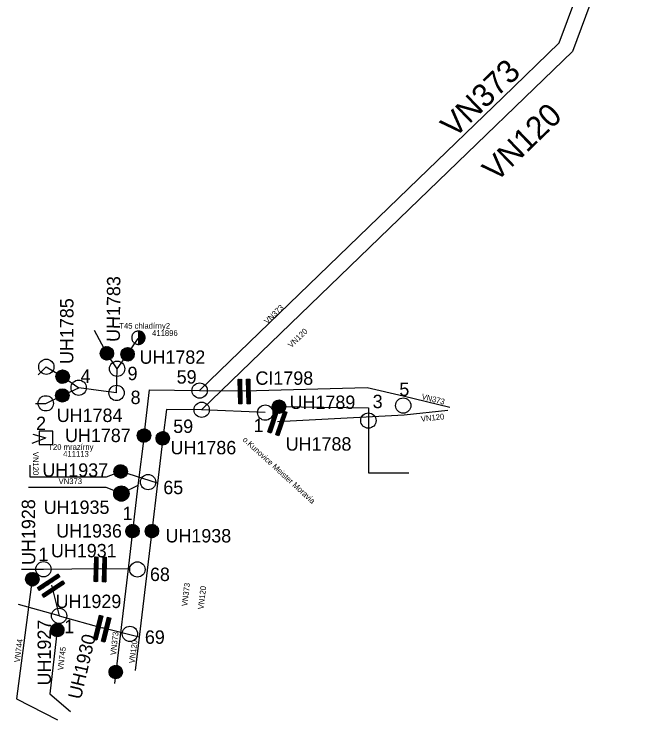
# Model space of a CAD drawing. Extents: x -540356 to -537233, y -1184040 to -1180351.
# Drawn here: x -540356 to -538730, y -1184040 to -1182196 of the extents above; entities that cross this region are included whole.
import ezdxf

# ---------------------------------------------------------------- set-up
doc = ezdxf.new("R2010")
doc.units = 0
for name, color, linetype in [('Default', 7, 'Continuous'), ('Vrstva 1', 7, 'Continuous'), ('Vrstva 2', 7, 'Continuous'), ('Vrstva 20', 7, 'Continuous'), ('Vrstva 3', 7, 'Continuous'), ('Vrstva 5', 7, 'Continuous')]:
    doc.layers.add(name, color=color, linetype=linetype)

# ---------------------------------------------------------------- blocks, each defined once
blk = doc.blocks.new('PS100')
at = {"layer": 'Default'}
for p, q in [((-17.5, -0.7), (0.7, 17.5)), ((-17.5, 0.7), (-0.7, 17.5)), ((-17.4, -2), (2, 17.4)), ((-17.3, 2.2), (-2.2, 17.3)), ((-17.2, -3.3), (3.3, 17.2)), ((-17, 4), (-4, 17)), ((-16.9, -4.4), (4.4, 16.9)), ((-16.6, -5.5), (5.5, 16.6)), ((-16.4, 6), (-6, 16.4)), ((-16.2, -6.5), (6.5, 16.2)), ((-15.8, -7.5), (7.5, 15.8)), ((-15.3, -8.4), (8.4, 15.3)), ((-15.2, 8.6), (-8.6, 15.2)), ((-14.8, -9.3), (9.3, 14.8)), ((-14.2, -10.2), (10.2, 14.2)), ((-13.6, -11), (11, 13.6)), ((-13, -11.7), (11.7, 13)), ((-12.3, -12.5), (12.5, 12.3)), ((-11.5, -13.2), (13.2, 11.5)), ((-10.8, -13.8), (13.8, 10.8)), ((-9.9, -14.4), (14.4, 9.9)), ((-9.1, -14.9), (14.9, 9.1)), ((-8.2, -15.5), (15.5, 8.2)), ((-7.2, -15.9), (15.9, 7.2)), ((-6.2, -16.3), (16.3, 6.2)), ((-5.2, -16.7), (16.7, 5.2)), ((-4.1, -17), (17, 4.1)), ((-2.9, -17.2), (17.2, 2.9)), ((-1.6, -17.4), (17.4, 1.6)), ((-0.3, -17.5), (17.5, 0.3)), ((1.1, -17.4), (17.4, -1.1)), ((2.7, -17.3), (17.3, -2.7)), ((4.5, -16.9), (16.9, -4.5)), ((6.7, -16.2), (16.2, -6.7)), ((9.7, -14.5), (14.5, -9.7))]:
    blk.add_line(p, q, dxfattribs=at)
blk.add_circle((0, 0), 17.5, dxfattribs=at)
blk = doc.blocks.new('PS140')
at = {"layer": 'Default'}
for p, q in [((-17.5, 0), (0, 17.5)), ((-17.4, -1.4), (1.4, 17.4)), ((-17.4, 1.5), (-1.5, 17.4)), ((-17.3, -2.6), (2.6, 17.3)), ((-17.2, 3.1), (-3.1, 17.2)), ((-17.1, -3.8), (3.8, 17.1)), ((-16.8, -4.9), (4.9, 16.8)), ((-16.8, 5), (-5, 16.8)), ((-16.4, -6), (6, 16.4)), ((-16, -7), (7, 16)), ((-15.9, 7.2), (-7.2, 15.9)), ((-15.6, -8), (8, 15.6)), ((-15.1, -8.9), (8.9, 15.1)), ((-14.5, -9.8), (9.8, 14.5)), ((-13.9, -10.6), (10.6, 13.9)), ((-13.8, 10.8), (-10.8, 13.8)), ((-13.3, -11.4), (11.4, 13.3)), ((-12.6, -12.1), (12.1, 12.6)), ((-11.9, -12.8), (12.8, 11.9)), ((-11.2, -13.5), (13.5, 11.2)), ((-10.4, -14.1), (14.1, 10.4)), ((-9.5, -14.7), (14.7, 9.5)), ((-8.6, -15.2), (15.2, 8.6)), ((-7.7, -15.7), (15.7, 7.7)), ((-6.7, -16.1), (16.1, 6.7)), ((-5.7, -16.5), (16.5, 5.7)), ((-4.6, -16.9), (16.9, 4.6)), ((-3.5, -17.1), (17.1, 3.5)), ((-2.3, -17.3), (17.3, 2.3)), ((-1, -17.5), (17.5, 1)), ((0.4, -17.5), (17.5, -0.4)), ((1.9, -17.4), (17.4, -1.9)), ((3.6, -17.1), (17.1, -3.6)), ((5.5, -16.6), (16.6, -5.5)), ((8, -15.6), (15.6, -8))]:
    blk.add_line(p, q, dxfattribs=at)
blk.add_circle((0, 0), 17.5, dxfattribs=at)
blk = doc.blocks.new('PS150')
at = {"layer": 'Default'}
for p, q in [((-15.1, 22.4), (-7.4, 30.1)), ((-15.1, 23.8), (-8.8, 30.1)), ((-15.1, 25.2), (-10.2, 30.1)), ((-15.1, 26.6), (-11.6, 30.1)), ((-15.1, 28), (-13, 30.1)), ((-15.1, 29.4), (-14.4, 30.1)), ((-15.1, 20.9), (-6.5, 29.5)), ((-15.1, 19.5), (-6.5, 28.1)), ((-15.1, 18.1), (-6.5, 26.7)), ((-15.1, 16.7), (-6.5, 25.3)), ((-15.1, 15.3), (-6.5, 23.9)), ((-15.1, 13.9), (-6.5, 22.4)), ((-15.1, 12.5), (-6.5, 21)), ((-15.1, 11), (-6.5, 19.6)), ((6.7, 22.6), (14.1, 30.1)), ((6.7, 24), (12.7, 30.1)), ((6.7, 25.4), (11.3, 30.1)), ((6.7, 26.8), (9.9, 30.1)), ((6.7, 28.3), (8.5, 30.1)), ((6.7, 29.7), (7, 30.1)), ((6.7, 21.2), (15.2, 29.8)), ((6.7, 19.8), (15.2, 28.3)), ((6.7, 18.4), (15.2, 26.9)), ((6.7, 16.9), (15.2, 25.5)), ((6.7, 15.5), (15.2, 24.1)), ((6.7, 14.1), (15.2, 22.7)), ((6.7, 12.7), (15.2, 21.3)), ((6.7, 11.3), (15.2, 19.9)), ((6.7, 9.9), (15.2, 18.4)), ((-15.1, 9.6), (-6.5, 18.2)), ((-15.1, 8.2), (-6.5, 16.8)), ((-15.1, 6.8), (-6.5, 15.4)), ((-15.1, 5.4), (-6.5, 14)), ((-15.1, 4), (-6.5, 12.5)), ((-15.1, 2.6), (-6.5, 11.1)), ((-15.1, 1.2), (-6.5, 9.7)), ((-15.1, -0.3), (-6.5, 8.3)), ((-15.1, -1.7), (-6.5, 6.9)), ((-15.1, -3.1), (-6.5, 5.5)), ((-15.1, -4.5), (-6.5, 4.1)), ((-15.1, -5.9), (-6.5, 2.6)), ((-15.1, -7.3), (-6.5, 1.2)), ((6.7, 8.5), (15.2, 17)), ((6.7, 7.1), (15.2, 15.6)), ((6.7, 5.6), (15.2, 14.2)), ((6.7, 4.2), (15.2, 12.8)), ((6.7, 2.8), (15.2, 11.4)), ((6.7, 1.4), (15.2, 10)), ((6.7, 0), (15.2, 8.5)), ((6.7, -1.4), (15.2, 7.1)), ((6.7, -2.8), (15.2, 5.7)), ((6.7, -4.3), (15.2, 4.3)), ((6.7, -5.7), (15.2, 2.9)), ((6.7, -7.1), (15.2, 1.5)), ((6.7, -8.5), (15.2, 0.1)), ((-15.1, -8.7), (-6.5, -0.2)), ((-15.1, -10.2), (-6.5, -1.6)), ((-15.1, -11.6), (-6.5, -3)), ((-15.1, -13), (-6.5, -4.4)), ((-15.1, -14.4), (-6.5, -5.8)), ((-15.1, -15.8), (-6.5, -7.3)), ((-15.1, -17.2), (-6.5, -8.7)), ((-15.1, -18.6), (-6.5, -10.1)), ((-15.1, -20.1), (-6.5, -11.5)), ((-15.1, -21.5), (-6.5, -12.9)), ((-15.1, -22.9), (-6.5, -14.3)), ((-15.1, -24.3), (-6.5, -15.7)), ((-15.1, -25.7), (-6.5, -17.2)), ((6.7, -9.9), (15.2, -1.4)), ((6.7, -11.3), (15.2, -2.8)), ((6.7, -12.7), (15.2, -4.2)), ((6.7, -14.2), (15.2, -5.6)), ((6.7, -15.6), (15.2, -7)), ((6.7, -17), (15.2, -8.4)), ((6.7, -18.4), (15.2, -9.8)), ((6.7, -19.8), (15.2, -11.3)), ((6.7, -21.2), (15.2, -12.7)), ((6.7, -22.6), (15.2, -14.1)), ((6.7, -24.1), (15.2, -15.5)), ((6.7, -25.5), (15.2, -16.9)), ((6.7, -26.9), (15.2, -18.3)), ((-15.1, -27.1), (-6.5, -18.6)), ((-15.1, -28.5), (-6.5, -20)), ((-15.1, -30), (-6.5, -21.4)), ((-15.1, -31.4), (-6.5, -22.8)), ((-15.1, -32.8), (-6.5, -24.2)), ((-15, -34.2), (-6.5, -25.6)), ((-13.6, -34.2), (-6.5, -27.1)), ((-12.2, -34.2), (-6.5, -28.5)), ((-10.8, -34.2), (-6.5, -29.9)), ((-9.4, -34.2), (-6.5, -31.3)), ((-8, -34.2), (-6.5, -32.7)), ((-6.5, -34.2), (-6.5, -34.1)), ((6.7, -28.3), (15.2, -19.7)), ((6.7, -29.7), (15.2, -21.2)), ((6.7, -31.1), (15.2, -22.6)), ((6.7, -32.5), (15.2, -24)), ((6.7, -34), (15.2, -25.4)), ((7.9, -34.2), (15.2, -26.8)), ((9.3, -34.2), (15.2, -28.2)), ((10.7, -34.2), (15.2, -29.6)), ((12.1, -34.2), (15.2, -31)), ((13.5, -34.2), (15.2, -32.5)), ((14.9, -34.2), (15.2, -33.9))]:
    blk.add_line(p, q, dxfattribs=at)
for points in [[(-6.5, 30.1), (-6.5, -34.2), (-15.1, -34.2), (-15.1, 30.1)], [(15.2, 30.1), (15.2, -34.2), (6.7, -34.2), (6.7, 30.1)]]:
    blk.add_lwpolyline(points, close=True, dxfattribs=at)
blk = doc.blocks.new('PS800')
at = {"layer": 'Vrstva 2'}
blk.add_circle((0, 0), 20, dxfattribs=at)
blk = doc.blocks.new('PS650')
at = {"layer": 'Vrstva 20'}
for points in [[(17.5, 17.5), (-17.5, 17.5)], [(-17.5, 17.5), (-17.5, -17.5)], [(17.5, -17.5), (17.5, 17.5)], [(-17.5, -17.5), (17.5, -17.5)]]:
    blk.add_lwpolyline(points, dxfattribs=at)
blk = doc.blocks.new('PS611')
at = {"layer": 'Default'}
for p, q in [((0, 16.2), (1.3, 17.4)), ((0, 14.7), (2.5, 17.3)), ((0, 13.3), (3.7, 17.1)), ((0, 11.9), (4.9, 16.8)), ((0, 10.5), (5.9, 16.4)), ((0, 9.1), (7, 16)), ((0, 7.7), (7.9, 15.6)), ((0, 6.3), (8.8, 15.1)), ((0, 4.8), (9.7, 14.5)), ((0, 3.4), (10.5, 14)), ((0, 2), (11.3, 13.3)), ((0, 0.6), (12, 12.7)), ((0, -0.8), (12.8, 12)), ((0, -2.2), (13.4, 11.2)), ((0, -3.6), (14, 10.4)), ((0, -5), (14.6, 9.6)), ((0, -6.5), (15.2, 8.7)), ((0, -7.9), (15.6, 7.8)), ((0, -9.3), (16.1, 6.8)), ((0, -10.7), (16.5, 5.8)), ((0, -12.1), (16.8, 4.7)), ((0, -13.5), (17.1, 3.6)), ((0, -14.9), (17.3, 2.4)), ((0, -16.4), (17.4, 1.1)), ((0.3, -17.5), (17.5, -0.3)), ((1.8, -17.4), (17.4, -1.8)), ((3.5, -17.1), (17.1, -3.5)), ((5.4, -16.7), (16.7, -5.4)), ((7.8, -15.7), (15.6, -7.8))]:
    blk.add_line(p, q, dxfattribs=at)
for points in [[(17.5, 0), (17.4, 1.8), (17.1, 3.6), (16.6, 5.4), (16, 7.1), (15.2, 8.8), (14.2, 10.3), (13, 11.7), (11.7, 13), (10.3, 14.2), (8.7, 15.2), (7.1, 16), (5.4, 16.6), (3.6, 17.1), (1.8, 17.4), (0, 17.5), (-1.8, 17.4), (-3.6, 17.1), (-5.4, 16.6), (-7.1, 16), (-8.8, 15.2), (-10.3, 14.2), (-11.7, 13), (-13, 11.7), (-14.2, 10.3), (-15.2, 8.7), (-16, 7.1), (-16.6, 5.4), (-17.1, 3.6), (-17.4, 1.8), (-17.5, 0), (-17.4, -1.8), (-17.1, -3.6), (-16.6, -5.4), (-16, -7.1), (-15.2, -8.8), (-14.2, -10.3), (-13, -11.7), (-11.7, -13), (-10.3, -14.2), (-8.8, -15.2), (-7.1, -16), (-5.4, -16.6), (-3.6, -17.1), (-1.8, -17.4), (0, -17.5), (1.8, -17.4), (3.6, -17.1), (5.4, -16.6), (7.1, -16), (8.8, -15.2), (10.3, -14.2), (11.7, -13), (13, -11.7), (14.2, -10.3), (15.2, -8.8), (16, -7.1), (16.6, -5.4), (17.1, -3.6), (17.4, -1.8), (17.5, 0)], [(0, 17.5), (0, -17.5)]]:
    blk.add_lwpolyline(points, dxfattribs=at)

msp = doc.modelspace()

# ---------------------------------------------------------------- linework, layer by layer
at = {"layer": 'Vrstva 1'}
for points in [[(-538730.2, -1181781.1), (-538745.8, -1181888.8), (-538896.2, -1182293.4), (-539271.4, -1182655.8), (-539865.4, -1183229.4)], [(-539078.2, -1182413.6), (-538930.5, -1182270.9), (-538802.3, -1181926.1), (-538823.3, -1181857.6)], [(-539298.4, -1182626.3), (-539078.2, -1182413.6)], [(-539870.7, -1183179.1), (-539298.4, -1182626.3)], [(-540113.1, -1183082), (-540145.5, -1183022.4)], [(-540059.1, -1183084.2), (-540031.4, -1183042.7)], [(-540086.3, -1183122.1), (-540113.1, -1183082)], [(-540086.3, -1183122.1), (-540059.1, -1183084.2)], [(-540293.2, -1183137.8), (-540271.5, -1183117.1)], [(-540271.5, -1183117.1), (-540228.8, -1183142.7)], [(-540087.9, -1183185.4), (-540086.3, -1183122.1)], [(-540228.8, -1183142.7), (-540186.9, -1183171.6)], [(-540229.7, -1183191.8), (-540186.9, -1183171.6)], [(-540135.2, -1183178.8), (-540186.9, -1183171.6)], [(-540087.9, -1183185.4), (-540135.2, -1183178.8)], [(-540016.1, -1183296.7), (-540001.7, -1183177.6), (-539870.7, -1183179.1)], [(-539870.7, -1183179.1), (-539754.1, -1183179.6)], [(-539754.1, -1183179.6), (-539433, -1183171.4), (-539338.5, -1183192.6)], [(-540272.9, -1183212.5), (-540229.7, -1183191.8)], [(-539338.5, -1183192.6), (-539216.9, -1183222.3)], [(-540299.6, -1183212.5), (-540272.9, -1183212.5)], [(-539865.4, -1183229.4), (-539957.4, -1183228.3), (-539967, -1183303.9)], [(-539699, -1183236.8), (-539865.4, -1183229.4), (-539865.4, -1183229.4)], [(-539663.2, -1183221.2), (-539429.6, -1183224.5), (-539429.6, -1183393.8), (-539324, -1183393.8)], [(-539335.9, -1183242.5), (-539221.9, -1183230.2)], [(-539666.8, -1183259.6), (-539335.9, -1183242.5)], [(-540308.5, -1183316.2), (-540272.4, -1183302.6)], [(-540306.5, -1183293.2), (-540272.4, -1183302.6)], [(-540016.1, -1183296.7), (-540032.2, -1183427.6)], [(-539967, -1183303.9), (-539980.5, -1183421.3)], [(-540077.1, -1183390.5), (-540115.2, -1183405.7), (-540313.4, -1183405.6), (-540313.4, -1183373.7)], [(-539980.5, -1183421.3), (-540077.1, -1183390.5)], [(-540075.3, -1183448.2), (-540115.1, -1183432.6), (-540318.4, -1183432.7)], [(-540032.1, -1183427.6), (-540075.3, -1183448.2)], [(-540032.1, -1183427.6), (-540046, -1183546.3)], [(-539980.5, -1183421.3), (-539995.6, -1183546.3)], [(-540046, -1183546.3), (-540057.8, -1183644.9)], [(-539995.6, -1183546.3), (-540028.8, -1183823.3)], [(-540336.7, -1183646.1), (-540278.9, -1183646)], [(-540278.9, -1183646), (-540130.6, -1183644.3)], [(-540130.6, -1183644.3), (-540057.8, -1183644.9)], [(-540057.8, -1183644.9), (-540090, -1183914.6)], [(-540308.1, -1183671.6), (-540349.2, -1183984.9), (-540242.7, -1184039.6)], [(-540257.8, -1183687.7), (-540238, -1183767.8)], [(-540238, -1183767.8), (-540344.6, -1183738.4)], [(-540238, -1183767.8), (-540125.1, -1183799.2)], [(-540242.9, -1183805.1), (-540262.2, -1183971.2), (-540208.6, -1184018)], [(-540028.8, -1183823.3), (-540125.1, -1183799.2)], [(-540028.8, -1183823.3), (-540039.2, -1183910.2)], [(-540090, -1183914.6), (-540093.3, -1183944.6)]]:
    msp.add_lwpolyline(points, dxfattribs=at)

# ---------------------------------------------------------------- block references
at = {"layer": 'Vrstva 2'}
for name, p, rotation in [('PS140', (-540113.1, -1183082), 107.19590279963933), ('PS140', (-540059.1, -1183084.2), -66.5734055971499), ('PS140', (-540228.8, -1183142.7), -28.299599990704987), ('PS150', (-539754.1, -1183179.6), 1.0974722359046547), ('PS140', (-540229.7, -1183191.8), -137.72051106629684), ('PS140', (-539663.2, -1183221.2), 43.89927496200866), ('PS150', (-539666.8, -1183259.6), -18.630803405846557), ('PS140', (-540016.1, -1183296.7), 84.6160527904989), ('PS140', (-539967, -1183303.9), 81.48321110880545), ('PS140', (-540077.1, -1183390.5), 7.688058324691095), ('PS140', (-540075.3, -1183448.2), 59.104705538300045), ('PS140', (-540046, -1183546.3), 82.97227774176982), ('PS140', (-539995.6, -1183546.3), -96.68660837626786), ('PS150', (-540130.6, -1183644.3), -1.1817719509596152), ('PS140', (-540308.1, -1183671.6), -5.999733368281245), ('PS150', (-540257.8, -1183687.7), -56.342046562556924), ('PS150', (-540125.1, -1183799.2), -13.995237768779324), ('PS100', (-540242.9, -1183805.1), -153.43188052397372), ('PS140', (-540090, -1183914.6), 70.46426947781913)]:
    msp.add_blockref(name, p, dxfattribs=dict(at, rotation=rotation))
at = {"layer": 'Vrstva 3'}
for name, p in [('PS611', (-540030.7, -1183041)), ('PS650', (-540272.4, -1183302.6))]:
    msp.add_blockref(name, p, dxfattribs=at)
at = {"layer": 'Vrstva 5'}
for p, rotation in [((-540271.5, -1183117.1), 81.87711381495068), ((-540086.3, -1183122.1), -14.150816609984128), ((-540186.9, -1183171.6), 79.52871106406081), ((-540087.9, -1183185.4), -10.367486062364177), ((-539870.7, -1183179.1), 5.629222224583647), ((-540272.9, -1183212.5), -78.54001944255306), ((-539338.4, -1183218.3), 4.80739434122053), ((-539865.4, -1183229.4), 5.814858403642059), ((-539699, -1183236.8), 5.99906389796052), ((-539429.6, -1183257.6), -14.14605001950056), ((-540005.5, -1183418.3), 84.0429694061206), ((-540075.3, -1183448.2), -70.16778056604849), ((-540075.3, -1183448.2), -93.51351665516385), ((-540278.9, -1183646), -7.290502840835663), ((-540033.5, -1183646.6), -9.78719996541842), ((-540238, -1183767.8), -24.336652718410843), ((-540052.9, -1183814.9), -19.91056951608)]:
    msp.add_blockref('PS800', p, dxfattribs=dict(at, rotation=rotation))

# ---------------------------------------------------------------- texts
at = {"layer": 'Vrstva 1'}
for s, height, rotation, p in [('VN373', 60, 44.007, (-539204.6, -1182521.6)), ('VN120', 60, 44.007, (-539095.8, -1182636.5)), ('VN373', 15, 44.008, (-539693.3, -1183006.6)), ('VN120', 15, 44, (-539631.1, -1183068.6)), ('VN373', 15, 346.262, (-539291.6, -1183201.6)), ('VN120', 15, 6.155, (-539291.5, -1183260.7)), ('o.Kunovice Meister Moravia', 15, 317.59, (-539759.5, -1183309.2)), ('VN120', 15, 270.233, (-540306.6, -1183339.2)), ('VN373', 15, 0.039, (-540239.4, -1183423.5)), ('VN373', 15, 83.207, (-539902.9, -1183743.4)), ('VN120', 15, 83.174, (-539860.6, -1183751.6)), ('VN373', 15, 83.635, (-540089.5, -1183871.2)), ('VN744', 15, 82.523, (-540340.8, -1183890.2)), ('VN120', 15, 82.563, (-540040.9, -1183892.7)), ('VN745', 15, 83.382, (-540227.2, -1183910.6))]:
    msp.add_text(s, height=height, rotation=rotation, dxfattribs=at).set_placement(p)
at = {"layer": 'Vrstva 2'}
for s, rotation, p in [('UH1783', 89.628, (-540079, -1183052.1)), ('UH1785', 89.849, (-540200.9, -1183109.8)), ('UH1928', 90.175, (-540300.4, -1183634.8)), ('UH1927', 90, (-540259.4, -1183949.6)), ('UH1930', 76.851, (-540181.2, -1183987.8))]:
    msp.add_text(s, height=35, rotation=rotation, dxfattribs=at).set_placement(p)
for s, p in [('UH1782', (-540027.7, -1183109.2)), ('CI1798', (-539724.7, -1183164.1)), ('UH1789', (-539635.5, -1183227.2)), ('UH1784', (-540244.2, -1183261.3)), ('UH1787', (-540222.6, -1183313.7)), ('UH1786', (-539946.7, -1183345.7)), ('UH1788', (-539645.7, -1183336.1)), ('UH1937', (-540281.7, -1183404.3)), ('UH1935', (-540278.2, -1183501.4)), ('UH1936', (-540245.6, -1183563.2)), ('UH1938', (-539959.9, -1183576)), ('UH1931', (-540259.4, -1183614.9)), ('UH1929', (-540247.2, -1183747.4))]:
    msp.add_text(s, height=35, dxfattribs=at).set_placement(p)
at = {"layer": 'Vrstva 3'}
for s, p in [('T45 chladírny2', (-540080.7, -1183017.5)), ('411896', (-539995, -1183036.3)), ('T20 mrazírny', (-540266.4, -1183334.1)), ('411113', (-540227.4, -1183352.1))]:
    msp.add_text(s, height=15, dxfattribs=at).set_placement(p)
at = {"layer": 'Vrstva 5'}
for s, p in [('4', (-540182.2, -1183159)), ('9', (-540059.1, -1183151.9)), ('59', (-539930.7, -1183160.9)), ('5', (-539348.6, -1183193.2)), ('8', (-540051.1, -1183214.4)), ('3', (-539418.3, -1183225.1)), ('2', (-540298.3, -1183282.4)), ('59', (-539939.7, -1183289.9)), ('1', (-539729.7, -1183287.8)), ('65', (-539965.6, -1183449.8)), ('1', (-540072.1, -1183517.5)), ('1', (-540292.1, -1183624.4)), ('68', (-540000.5, -1183676.8)), ('1', (-540224.8, -1183813.1)), ('69', (-540013.8, -1183840.8))]:
    msp.add_text(s, height=35, dxfattribs=at).set_placement(p)

doc.saveas('drawing.dxf')
